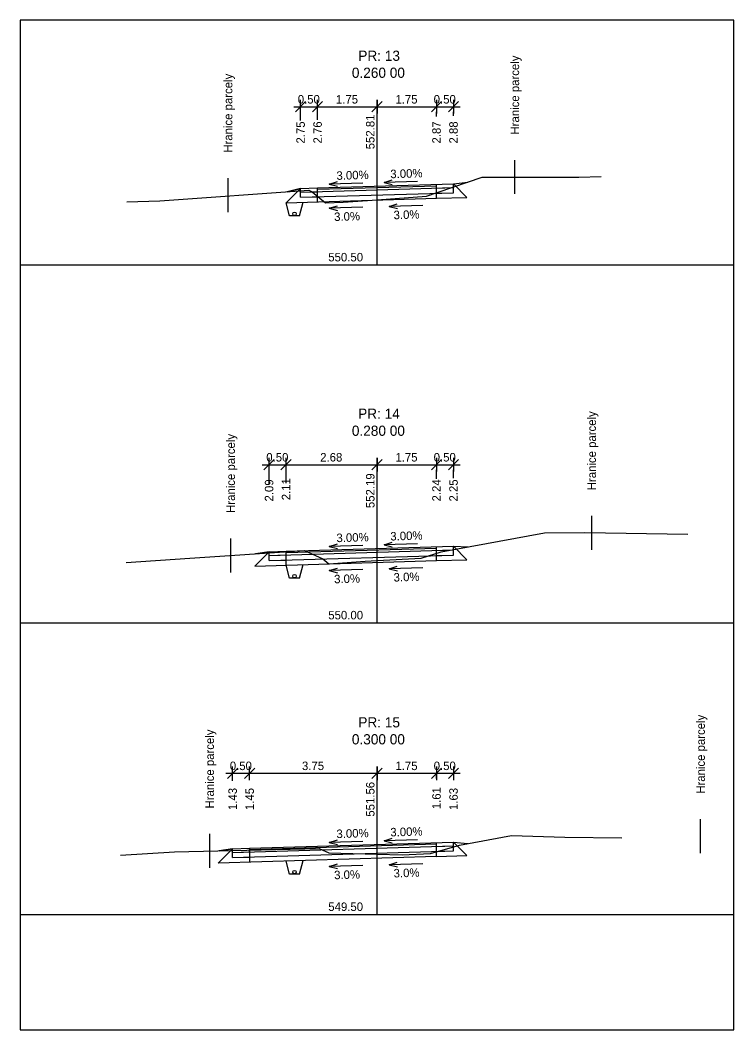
# Model space of a CAD drawing. Extents: x -603737 to -603383, y -1112154 to -1112124.
# Drawn here: x -603610.7 to -603589.7, y -1112153.84 to -1112124.14 of the extents above; entities that cross this region are included whole.
import ezdxf

# ---------------------------------------------------------------- set-up
doc = ezdxf.new("R2010")
doc.units = 0
for name, color, linetype in [('_křivky z hran', 7, 'Continuous'), ('_netisk', 7, 'Continuous'), ('C3D_Podsestava-Popis', 7, 'Continuous'), ('C3D_PP-Popisek', 7, 'Continuous'), ('C3D_PR', 7, 'Continuous'), ('C3D_ZPR', 7, 'Continuous'), ('Default', 7, 'Continuous'), ('konstrukce', 7, 'Continuous')]:
    doc.layers.add(name, color=color, linetype=linetype)

# ---------------------------------------------------------------- blocks, each defined once
blk = doc.blocks.new('_Oblique')
at = {"layer": 'Default'}
blk.add_line((-0.5, -0.5), (0.5, 0.5), dxfattribs=at)
blk = doc.blocks.new('AeccTickLine')
at = {"layer": 'Default'}
blk.add_line((0, 1), (0, -1), dxfattribs=at)

msp = doc.modelspace()

# ---------------------------------------------------------------- linework, layer by layer
at = {"layer": '_netisk'}
msp.add_lwpolyline([(-603610.702, -1112153.84), (-603589.702, -1112153.84), (-603589.702, -1112124.14), (-603610.702, -1112124.14)], close=True, dxfattribs=at)
at = {"layer": 'C3D_Podsestava-Popis'}
for p, q in [((-603602.652, -1112126.686), (-603600.202, -1112126.686)), ((-603602.452, -1112127.09), (-603602.452, -1112126.836)), ((-603601.952, -1112127.075), (-603601.952, -1112126.836)), ((-603600.202, -1112126.686), (-603597.752, -1112126.686)), ((-603600.202, -1112127.022), (-603600.202, -1112126.836)), ((-603598.452, -1112126.97), (-603598.452, -1112126.836)), ((-603597.952, -1112126.955), (-603597.952, -1112126.836)), ((-603603.579, -1112137.217), (-603600.202, -1112137.217)), ((-603600.202, -1112137.217), (-603597.752, -1112137.217)), ((-603603.379, -1112137.776), (-603603.379, -1112137.367)), ((-603602.879, -1112137.761), (-603602.879, -1112137.367)), ((-603600.202, -1112137.68), (-603600.202, -1112137.367)), ((-603598.452, -1112137.628), (-603598.452, -1112137.367)), ((-603597.952, -1112137.613), (-603597.952, -1112137.367)), ((-603604.652, -1112146.294), (-603600.202, -1112146.294)), ((-603604.452, -1112146.513), (-603604.452, -1112146.444)), ((-603603.952, -1112146.498), (-603603.952, -1112146.444)), ((-603600.202, -1112146.294), (-603597.752, -1112146.294)), ((-603600.202, -1112146.444), (-603600.202, -1112146.385)), ((-603598.452, -1112146.444), (-603598.452, -1112146.333)), ((-603597.952, -1112146.318), (-603597.952, -1112146.444))]:
    msp.add_line(p, q, dxfattribs=at)
at = {"layer": 'C3D_PP-Popisek'}
for p, q in [((-603601.605, -1112128.964), (-603601.369, -1112128.889)), ((-603600.621, -1112128.935), (-603601.605, -1112128.964)), ((-603601.605, -1112128.964), (-603601.364, -1112129.025)), ((-603599.994, -1112128.916), (-603599.757, -1112128.84)), ((-603599.01, -1112128.886), (-603599.994, -1112128.916)), ((-603599.994, -1112128.916), (-603599.753, -1112128.977)), ((-603599.841, -1112129.621), (-603599.604, -1112129.546)), ((-603601.605, -1112129.674), (-603601.369, -1112129.599)), ((-603600.621, -1112129.645), (-603601.605, -1112129.674)), ((-603601.605, -1112129.674), (-603601.364, -1112129.735)), ((-603598.857, -1112129.592), (-603599.841, -1112129.621)), ((-603599.841, -1112129.621), (-603599.6, -1112129.682)), ((-603601.605, -1112139.623), (-603601.369, -1112139.547)), ((-603600.621, -1112139.593), (-603601.605, -1112139.623)), ((-603601.605, -1112139.623), (-603601.364, -1112139.684)), ((-603599.994, -1112139.574), (-603599.757, -1112139.499)), ((-603599.01, -1112139.544), (-603599.994, -1112139.574)), ((-603599.994, -1112139.574), (-603599.753, -1112139.635)), ((-603601.605, -1112140.333), (-603601.369, -1112140.257)), ((-603599.841, -1112140.28), (-603599.604, -1112140.204)), ((-603598.857, -1112140.25), (-603599.841, -1112140.28)), ((-603600.621, -1112140.303), (-603601.605, -1112140.333)), ((-603601.605, -1112140.333), (-603601.364, -1112140.394)), ((-603599.841, -1112140.28), (-603599.6, -1112140.341)), ((-603601.605, -1112148.327), (-603601.369, -1112148.252)), ((-603599.994, -1112148.279), (-603599.757, -1112148.203)), ((-603599.01, -1112148.249), (-603599.994, -1112148.279)), ((-603599.994, -1112148.279), (-603599.753, -1112148.34)), ((-603603.952, -1112148.498), (-603603.952, -1112148.908)), ((-603600.621, -1112148.298), (-603601.605, -1112148.327)), ((-603601.605, -1112148.327), (-603601.364, -1112148.388)), ((-603601.605, -1112149.037), (-603601.369, -1112148.962)), ((-603600.621, -1112149.008), (-603601.605, -1112149.037)), ((-603601.605, -1112149.037), (-603601.364, -1112149.098)), ((-603599.841, -1112148.984), (-603599.604, -1112148.909)), ((-603598.857, -1112148.955), (-603599.841, -1112148.984)), ((-603599.841, -1112148.984), (-603599.6, -1112149.046))]:
    msp.add_line(p, q, dxfattribs=at)
at = {"layer": 'C3D_PR'}
for points in [[(-603607.567, -1112129.487), (-603606.59, -1112129.455), (-603602.21, -1112129.139), (-603602.114, -1112129.185), (-603601.718, -1112129.513), (-603601.196, -1112129.494), (-603600.202, -1112129.424), (-603598.75, -1112129.321), (-603598.404, -1112129.203), (-603597.103, -1112128.761), (-603594.259, -1112128.754), (-603593.601, -1112128.739)], [(-603607.579, -1112140.091), (-603605.713, -1112139.961), (-603602.333, -1112139.744), (-603601.794, -1112139.986), (-603601.621, -1112140.13), (-603600.553, -1112140.057), (-603600.202, -1112140.039), (-603598.9, -1112139.97), (-603598.313, -1112139.775), (-603595.275, -1112139.217), (-603594.085, -1112139.214), (-603591.059, -1112139.258)], [(-603607.75, -1112148.706), (-603606.166, -1112148.604), (-603601.907, -1112148.502), (-603601.621, -1112148.63), (-603600.202, -1112148.673), (-603599.461, -1112148.696), (-603598.632, -1112148.652), (-603597.779, -1112148.41), (-603596.243, -1112148.125), (-603594.677, -1112148.171), (-603592.999, -1112148.188)]]:
    msp.add_lwpolyline(points, dxfattribs=at)
at = {"layer": 'C3D_ZPR'}
for p, q in [((-603600.202, -1112131.336), (-603600.202, -1112126.836)), ((-603596.145, -1112129.253), (-603596.145, -1112128.253)), ((-603604.585, -1112129.788), (-603604.585, -1112128.788)), ((-603601.952, -1112129.075), (-603597.952, -1112128.955)), ((-603598.452, -1112129.01), (-603598.452, -1112128.97)), ((-603598.452, -1112129.38), (-603598.452, -1112128.97)), ((-603597.952, -1112128.955), (-603597.527, -1112128.905)), ((-603597.952, -1112128.955), (-603597.527, -1112128.905)), ((-603597.952, -1112129.215), (-603597.952, -1112128.955)), ((-603597.952, -1112129.215), (-603597.952, -1112128.955)), ((-603597.952, -1112128.955), (-603597.554, -1112129.353)), ((-603602.875, -1112129.512), (-603602.452, -1112129.09)), ((-603602.452, -1112129.09), (-603602.847, -1112129.185)), ((-603602.847, -1112129.185), (-603602.452, -1112129.09)), ((-603602.452, -1112129.2), (-603597.952, -1112129.065)), ((-603602.452, -1112129.09), (-603601.952, -1112129.075)), ((-603602.452, -1112129.35), (-603602.452, -1112129.09)), ((-603602.452, -1112129.35), (-603602.452, -1112129.09)), ((-603602.452, -1112129.2), (-603601.952, -1112129.185)), ((-603602.452, -1112129.35), (-603597.952, -1112129.215)), ((-603601.952, -1112129.115), (-603598.452, -1112129.01)), ((-603601.952, -1112129.485), (-603601.952, -1112129.075)), ((-603601.952, -1112129.185), (-603601.952, -1112129.115)), ((-603598.452, -1112129.08), (-603597.952, -1112129.065)), ((-603598.452, -1112129.23), (-603598.452, -1112129.08)), ((-603598.452, -1112129.23), (-603597.952, -1112129.215)), ((-603602.875, -1112129.512), (-603598.452, -1112129.38)), ((-603602.452, -1112129.35), (-603601.952, -1112129.335)), ((-603601.952, -1112129.485), (-603601.952, -1112129.335)), ((-603598.452, -1112129.38), (-603597.554, -1112129.353)), ((-603610.702, -1112131.336), (-603589.702, -1112131.336)), ((-603600.202, -1112141.867), (-603600.202, -1112137.367)), ((-603593.885, -1112139.717), (-603593.885, -1112138.717)), ((-603604.508, -1112140.384), (-603604.508, -1112139.384)), ((-603602.879, -1112139.761), (-603597.952, -1112139.613)), ((-603598.452, -1112139.668), (-603598.452, -1112139.628)), ((-603598.452, -1112140.038), (-603598.452, -1112139.628)), ((-603597.952, -1112139.873), (-603597.952, -1112139.613)), ((-603597.952, -1112139.873), (-603597.952, -1112139.613)), ((-603597.952, -1112139.613), (-603597.554, -1112140.011)), ((-603597.952, -1112139.613), (-603597.527, -1112139.63)), ((-603597.952, -1112139.613), (-603597.527, -1112139.63)), ((-603603.802, -1112140.198), (-603603.379, -1112139.776)), ((-603603.379, -1112139.776), (-603603.774, -1112139.837)), ((-603603.774, -1112139.837), (-603603.379, -1112139.776)), ((-603603.379, -1112139.886), (-603597.952, -1112139.723)), ((-603603.379, -1112139.776), (-603602.879, -1112139.761)), ((-603603.379, -1112140.036), (-603603.379, -1112139.776)), ((-603603.379, -1112140.036), (-603603.379, -1112139.776)), ((-603603.379, -1112139.886), (-603602.879, -1112139.871)), ((-603603.379, -1112140.036), (-603597.952, -1112139.873)), ((-603602.879, -1112139.801), (-603598.452, -1112139.668)), ((-603602.879, -1112140.171), (-603602.879, -1112139.761)), ((-603602.879, -1112139.871), (-603602.879, -1112139.801)), ((-603598.452, -1112139.738), (-603597.952, -1112139.723)), ((-603598.452, -1112139.888), (-603598.452, -1112139.738)), ((-603598.452, -1112139.888), (-603597.952, -1112139.873)), ((-603603.802, -1112140.198), (-603598.452, -1112140.038)), ((-603603.379, -1112140.036), (-603602.879, -1112140.021)), ((-603602.879, -1112140.171), (-603602.879, -1112140.021)), ((-603598.452, -1112140.038), (-603597.554, -1112140.011)), ((-603610.702, -1112141.867), (-603589.702, -1112141.867)), ((-603600.202, -1112150.444), (-603600.202, -1112146.444)), ((-603590.679, -1112148.645), (-603590.679, -1112147.645)), ((-603605.126, -1112149.079), (-603605.126, -1112148.079)), ((-603604.875, -1112148.935), (-603604.452, -1112148.513)), ((-603604.452, -1112148.513), (-603604.847, -1112148.572)), ((-603604.847, -1112148.572), (-603604.452, -1112148.513)), ((-603604.452, -1112148.623), (-603597.952, -1112148.428)), ((-603604.452, -1112148.513), (-603603.952, -1112148.498)), ((-603604.452, -1112148.773), (-603604.452, -1112148.513)), ((-603604.452, -1112148.773), (-603604.452, -1112148.513)), ((-603603.952, -1112148.498), (-603597.952, -1112148.318)), ((-603603.952, -1112148.538), (-603598.452, -1112148.373)), ((-603603.952, -1112148.608), (-603603.952, -1112148.538)), ((-603598.452, -1112148.373), (-603598.452, -1112148.333)), ((-603598.452, -1112148.743), (-603598.452, -1112148.333)), ((-603598.452, -1112148.443), (-603597.952, -1112148.428)), ((-603598.452, -1112148.593), (-603598.452, -1112148.443)), ((-603597.952, -1112148.578), (-603597.952, -1112148.318)), ((-603597.952, -1112148.578), (-603597.952, -1112148.318)), ((-603597.952, -1112148.318), (-603597.554, -1112148.716)), ((-603597.952, -1112148.318), (-603597.527, -1112148.364)), ((-603597.952, -1112148.318), (-603597.527, -1112148.364)), ((-603598.452, -1112148.743), (-603604.875, -1112148.935)), ((-603604.452, -1112148.773), (-603597.952, -1112148.578)), ((-603604.452, -1112148.623), (-603603.952, -1112148.608)), ((-603604.452, -1112148.773), (-603603.952, -1112148.758)), ((-603598.452, -1112148.593), (-603597.952, -1112148.578)), ((-603598.452, -1112148.743), (-603597.554, -1112148.716)), ((-603610.702, -1112150.444), (-603589.702, -1112150.444))]:
    msp.add_line(p, q, dxfattribs=at)
at = {"layer": 'konstrukce'}
for p, q in [((-603602.779, -1112129.897), (-603602.875, -1112129.512)), ((-603602.479, -1112129.897), (-603602.379, -1112129.497)), ((-603602.479, -1112129.897), (-603602.779, -1112129.897)), ((-603602.779, -1112140.556), (-603602.875, -1112140.171)), ((-603602.479, -1112140.556), (-603602.379, -1112140.156)), ((-603602.479, -1112140.556), (-603602.779, -1112140.556)), ((-603602.479, -1112149.261), (-603602.379, -1112148.861)), ((-603602.779, -1112149.261), (-603602.875, -1112148.875)), ((-603602.479, -1112149.261), (-603602.779, -1112149.261))]:
    msp.add_line(p, q, dxfattribs=at)
for centre in [(-603602.629, -1112129.837), (-603602.629, -1112140.496), (-603602.629, -1112149.201)]:
    msp.add_circle(centre, 0.05, dxfattribs=at)

# ---------------------------------------------------------------- block references
at = {"layer": '_křivky z hran', "rotation": 180}
for name, p, xscale, yscale in [('_Oblique', (-603602.452, -1112126.686), 0.3, 0.3), ('AeccTickLine', (-603602.452, -1112126.686), 0.2, 0.20000000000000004), ('_Oblique', (-603601.952, -1112126.686), 0.3, 0.3), ('AeccTickLine', (-603601.952, -1112126.686), 0.2, 0.20000000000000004), ('_Oblique', (-603600.202, -1112126.686), 0.3, 0.3), ('AeccTickLine', (-603600.202, -1112126.686), 0.2, 0.20000000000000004), ('_Oblique', (-603603.379, -1112137.217), 0.3, 0.3), ('AeccTickLine', (-603603.379, -1112137.217), 0.2, 0.20000000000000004), ('_Oblique', (-603602.879, -1112137.217), 0.3, 0.3), ('AeccTickLine', (-603602.879, -1112137.217), 0.2, 0.20000000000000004), ('_Oblique', (-603600.202, -1112137.217), 0.3, 0.3), ('AeccTickLine', (-603600.202, -1112137.217), 0.2, 0.20000000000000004), ('_Oblique', (-603604.452, -1112146.294), 0.3, 0.3), ('AeccTickLine', (-603604.452, -1112146.294), 0.2, 0.20000000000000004), ('_Oblique', (-603603.952, -1112146.294), 0.3, 0.3), ('AeccTickLine', (-603603.952, -1112146.294), 0.2, 0.20000000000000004), ('_Oblique', (-603600.202, -1112146.294), 0.3, 0.3), ('AeccTickLine', (-603600.202, -1112146.294), 0.2, 0.20000000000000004)]:
    msp.add_blockref(name, p, dxfattribs=dict(at, xscale=xscale, yscale=yscale))
at = {"layer": '_křivky z hran'}
for name, p, xscale, yscale in [('_Oblique', (-603600.202, -1112126.686), 0.3, 0.3), ('AeccTickLine', (-603600.202, -1112126.686), 0.2, 0.20000000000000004), ('_Oblique', (-603598.452, -1112126.686), 0.3, 0.3), ('AeccTickLine', (-603598.452, -1112126.686), 0.2, 0.20000000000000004), ('_Oblique', (-603597.952, -1112126.686), 0.3, 0.3), ('AeccTickLine', (-603597.952, -1112126.686), 0.2, 0.20000000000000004), ('_Oblique', (-603600.202, -1112137.217), 0.3, 0.3), ('AeccTickLine', (-603600.202, -1112137.217), 0.2, 0.20000000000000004), ('_Oblique', (-603598.452, -1112137.217), 0.3, 0.3), ('AeccTickLine', (-603598.452, -1112137.217), 0.2, 0.20000000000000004), ('_Oblique', (-603597.952, -1112137.217), 0.3, 0.3), ('AeccTickLine', (-603597.952, -1112137.217), 0.2, 0.20000000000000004), ('_Oblique', (-603600.202, -1112146.294), 0.3, 0.3), ('AeccTickLine', (-603600.202, -1112146.294), 0.2, 0.20000000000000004), ('_Oblique', (-603598.452, -1112146.294), 0.3, 0.3), ('AeccTickLine', (-603598.452, -1112146.294), 0.2, 0.20000000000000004), ('_Oblique', (-603597.952, -1112146.294), 0.3, 0.3), ('AeccTickLine', (-603597.952, -1112146.294), 0.2, 0.20000000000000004)]:
    msp.add_blockref(name, p, dxfattribs=dict(at, xscale=xscale, yscale=yscale))

# ---------------------------------------------------------------- texts
at = {"layer": 'C3D_Podsestava-Popis'}
for s, rotation, p in [('0.50', 360, (-603602.534, -1112126.592)), ('1.75', 360, (-603601.41, -1112126.592)), ('1.75', 360, (-603601.41, -1112126.592)), ('1.75', 360, (-603599.66, -1112126.592)), ('1.75', 360, (-603599.66, -1112126.592)), ('0.50', 360, (-603598.534, -1112126.592)), ('2.75', 90, (-603602.326, -1112127.769)), ('2.75', 90, (-603602.326, -1112127.769)), ('2.76', 90, (-603601.826, -1112127.768)), ('552.81', 90, (-603600.276, -1112127.938)), ('2.87', 90, (-603598.326, -1112127.768)), ('2.88', 90, (-603597.826, -1112127.768)), ('2.88', 90, (-603597.826, -1112127.768)), ('3.00%', 1.7184, (-603601.392, -1112128.838)), ('3.00%', 1.7184, (-603599.807, -1112128.79)), ('3.0%', 1.7184, (-603601.46, -1112130.049)), ('3.0%', 1.7184, (-603599.71, -1112129.997)), ('0.50', 360, (-603603.46, -1112137.123)), ('2.68', 360, (-603601.873, -1112137.123)), ('2.68', 360, (-603601.873, -1112137.123)), ('1.75', 360, (-603599.66, -1112137.123)), ('1.75', 360, (-603599.66, -1112137.123)), ('0.50', 360, (-603598.534, -1112137.123)), ('552.19', 90, (-603600.276, -1112138.493)), ('2.09', 90, (-603603.253, -1112138.299)), ('2.09', 90, (-603603.253, -1112138.299)), ('2.11', 90, (-603602.753, -1112138.262)), ('2.24', 90, (-603598.326, -1112138.298)), ('2.25', 90, (-603597.826, -1112138.3)), ('2.25', 90, (-603597.826, -1112138.3)), ('3.00%', 1.7184, (-603601.392, -1112139.496)), ('3.00%', 1.7184, (-603599.807, -1112139.448)), ('3.0%', 1.7184, (-603601.46, -1112140.707)), ('3.0%', 1.7184, (-603599.71, -1112140.655)), ('0.50', 360, (-603604.534, -1112146.2)), ('3.75', 360, (-603602.41, -1112146.2)), ('3.75', 360, (-603602.41, -1112146.2)), ('1.75', 360, (-603599.66, -1112146.2)), ('1.75', 360, (-603599.66, -1112146.2)), ('0.50', 360, (-603598.534, -1112146.2)), ('1.43', 90, (-603604.326, -1112147.375)), ('1.43', 90, (-603604.326, -1112147.375)), ('1.45', 90, (-603603.826, -1112147.376)), ('551.56', 90, (-603600.276, -1112147.57)), ('1.61', 90, (-603598.326, -1112147.351)), ('1.63', 90, (-603597.826, -1112147.375)), ('1.63', 90, (-603597.826, -1112147.375)), ('3.00%', 1.7184, (-603601.392, -1112148.201)), ('3.00%', 1.7184, (-603599.807, -1112148.153)), ('3.0%', 1.7184, (-603601.46, -1112149.412)), ('3.0%', 1.7184, (-603599.71, -1112149.36))]:
    msp.add_text(s, height=0.25, rotation=rotation, dxfattribs=at).set_placement(p)
at = {"layer": 'C3D_ZPR'}
for s, p in [('PR: 13', (-603600.752, -1112125.336)), ('0.260 00', (-603600.942, -1112125.836)), ('PR: 14', (-603600.757, -1112135.867)), ('0.280 00', (-603600.942, -1112136.367)), ('PR: 15', (-603600.752, -1112144.944)), ('0.300 00', (-603600.942, -1112145.444))]:
    msp.add_text(s, height=0.3, dxfattribs=at).set_placement(p)
for s, rotation, p in [('Hranice parcely', 90, (-603596.02, -1112127.503)), ('Hranice parcely', 90, (-603604.46, -1112128.038)), ('550.50', 360, (-603601.635, -1112131.236)), ('Hranice parcely', 90, (-603593.76, -1112137.967)), ('Hranice parcely', 90, (-603604.383, -1112138.634)), ('550.00', 360, (-603601.635, -1112141.767)), ('Hranice parcely', 90, (-603590.554, -1112146.895)), ('Hranice parcely', 90, (-603605.001, -1112147.329)), ('549.50', 360, (-603601.635, -1112150.344))]:
    msp.add_text(s, height=0.25, rotation=rotation, dxfattribs=at).set_placement(p)

doc.saveas('drawing.dxf')
